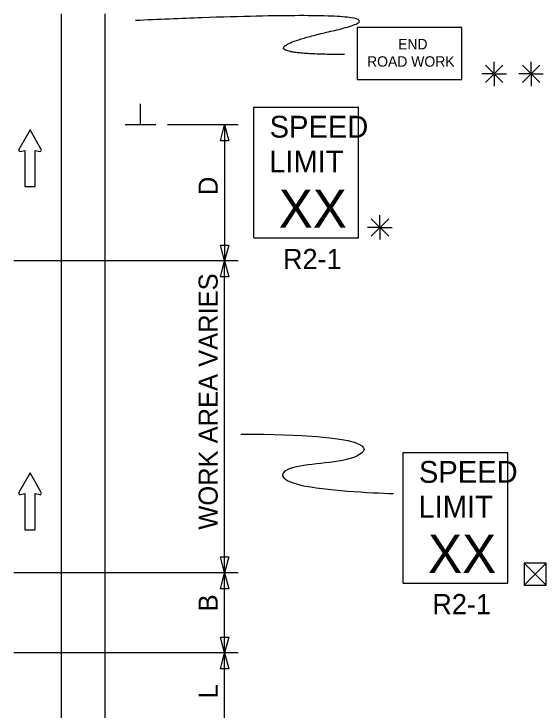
# Model space of a CAD drawing. Extents: x 16364 to 18480, y 5564 to 6927.
# Drawn here: x 16936.6 to 17132, y 6671 to 6926.7 of the extents above; entities that cross this region are included whole.
import ezdxf

# ---------------------------------------------------------------- set-up
doc = ezdxf.new("R2010")
doc.units = 0
for name, color, linetype in [('MT_SCRATCH_LEVEL_E', 7, 'Continuous'), ('PAVT_EDGE_EX', 7, 'Continuous'), ('TRAFFIC_SIGNS_PR', 7, 'Continuous'), ('TYPICAL_TEXT_DIMEN_PR', 7, 'Continuous')]:
    doc.layers.add(name, color=color, linetype=linetype)

msp = doc.modelspace()

# ---------------------------------------------------------------- linework, layer by layer
at = {"layer": 'MT_SCRATCH_LEVEL_E'}
for p, q in [((16942.49, 6884.13), (16938.38, 6876.89)), ((16946.64, 6876.89), (16942.49, 6884.13)), ((16938.86, 6876.2), (16940.64, 6876.52)), ((16940.64, 6876.52), (16940.64, 6863.26)), ((16944.38, 6863.26), (16944.38, 6876.52)), ((16944.38, 6876.52), (16946.16, 6876.2)), ((16940.64, 6863.26), (16944.38, 6863.26)), ((16942.49, 6758.11), (16938.38, 6750.87)), ((16946.64, 6750.87), (16942.49, 6758.11)), ((16938.86, 6750.18), (16940.64, 6750.5)), ((16940.64, 6750.5), (16940.64, 6737.24)), ((16944.38, 6737.24), (16944.38, 6750.5)), ((16944.38, 6750.5), (16946.16, 6750.18)), ((16940.64, 6737.24), (16944.38, 6737.24))]:
    msp.add_line(p, q, dxfattribs=at)
for centre, start, end in [((16938.79, 6876.66), 150.4248, 279.9638), ((16946.23, 6876.66), 260.0362, 29.7731), ((16938.79, 6750.64), 150.4248, 279.9638), ((16946.23, 6750.64), 260.0362, 29.7731)]:
    msp.add_arc(centre, 0.463, start, end, dxfattribs=at)
at = {"layer": 'PAVT_EDGE_EX'}
for p, q in [((16953.97, 6926.69), (16953.97, 5953.59)), ((16969.97, 6926.69), (16969.97, 5953.59))]:
    msp.add_line(p, q, dxfattribs=at)
at = {"layer": 'TRAFFIC_SIGNS_PR'}
for p, q in [((17024.72, 6892.4), (17063.12, 6892.4)), ((17024.72, 6844.4), (17024.72, 6892.4)), ((17063.12, 6844.4), (17063.12, 6892.4)), ((17024.72, 6844.4), (17063.12, 6844.4)), ((17079.58, 6765.64), (17117.98, 6765.64)), ((17079.58, 6717.64), (17079.58, 6765.64)), ((17117.98, 6717.64), (17117.98, 6765.64)), ((17079.58, 6717.64), (17117.98, 6717.64))]:
    msp.add_line(p, q, dxfattribs=at)
msp.add_lwpolyline([(17062.69, 6902.56), (17101.09, 6902.56), (17101.09, 6921.76), (17062.69, 6921.76)], close=True, dxfattribs=at)
msp.add_open_spline([(17057.97, 6911.79), (17015.46, 6911.79), (17091.98, 6929.21), (16981.19, 6924.27)], degree=2, dxfattribs=at)
at = {"layer": 'TYPICAL_TEXT_DIMEN_PR'}
for p, q in [((17113.02, 6904.69), (17113.02, 6909.14)), ((17126.53, 6904.69), (17126.53, 6909.14)), ((17116.21, 6907.88), (17109.83, 6901.5)), ((17109.84, 6907.88), (17116.21, 6901.5)), ((17123.34, 6907.88), (17129.72, 6901.5)), ((17129.72, 6907.88), (17123.34, 6901.5)), ((17113.02, 6904.69), (17108.49, 6904.69)), ((17113.02, 6904.69), (17116.21, 6904.69)), ((17113.02, 6904.69), (17117.5, 6904.69)), ((17113.02, 6904.69), (17113.02, 6900.19)), ((17126.53, 6904.69), (17122, 6904.69)), ((17126.53, 6904.69), (17129.72, 6904.69)), ((17126.53, 6904.69), (17131.01, 6904.69)), ((17126.53, 6904.69), (17126.53, 6900.19)), ((16983.09, 6885.95), (16983.09, 6893.73)), ((16988.72, 6885.95), (16977.47, 6885.95)), ((17018.97, 6885.95), (16992.97, 6885.95)), ((17012.4, 6880.08), (17013.97, 6885.95)), ((17013.97, 6885.95), (17013.97, 6835.95)), ((17013.97, 6885.95), (17015.54, 6880.08)), ((17013.97, 6880.08), (17012.4, 6880.08)), ((17015.54, 6880.08), (17013.97, 6880.08)), ((17071.04, 6848.31), (17071.04, 6852.76)), ((17074.23, 6851.49), (17067.85, 6845.12)), ((17067.86, 6851.49), (17074.23, 6845.12)), ((17071.04, 6848.31), (17066.51, 6848.31)), ((17071.04, 6848.31), (17074.23, 6848.31)), ((17071.04, 6848.31), (17075.52, 6848.31)), ((17071.04, 6848.31), (17071.04, 6843.81)), ((17013.97, 6835.95), (17012.4, 6841.81)), ((17012.4, 6841.81), (17013.97, 6841.81)), ((17013.97, 6841.81), (17015.54, 6841.81)), ((17015.54, 6841.81), (17013.97, 6835.95)), ((17018.97, 6835.95), (16936.57, 6835.95)), ((17012.4, 6830.08), (17013.97, 6835.95)), ((17013.97, 6721.41), (17013.97, 6835.95)), ((17013.97, 6835.95), (17015.54, 6830.08)), ((17013.97, 6830.08), (17012.4, 6830.08)), ((17015.54, 6830.08), (17013.97, 6830.08)), ((17013.97, 6721.41), (17012.4, 6727.27)), ((17012.4, 6727.27), (17013.97, 6727.27)), ((17013.97, 6727.27), (17015.54, 6727.27)), ((17015.54, 6727.27), (17013.97, 6721.41)), ((17124.05, 6724.91), (17132.05, 6716.91)), ((17124.05, 6716.91), (17132.05, 6724.91)), ((17018.97, 6721.41), (16936.57, 6721.41)), ((17012.4, 6715.55), (17013.97, 6721.41)), ((17013.97, 6691.98), (17013.97, 6721.41)), ((17013.97, 6721.41), (17015.54, 6715.55)), ((17013.97, 6715.55), (17012.4, 6715.55)), ((17015.54, 6715.55), (17013.97, 6715.55)), ((17013.97, 6691.98), (17012.4, 6697.84)), ((17012.4, 6697.84), (17013.97, 6697.84)), ((17013.97, 6697.84), (17015.54, 6697.84)), ((17015.54, 6697.84), (17013.97, 6691.98)), ((17018.97, 6691.98), (16936.57, 6691.98)), ((17012.4, 6686.12), (17013.97, 6691.98)), ((17013.97, 6661.42), (17013.97, 6691.98)), ((17013.97, 6691.98), (17015.54, 6686.12)), ((17013.97, 6686.12), (17012.4, 6686.12)), ((17015.54, 6686.12), (17013.97, 6686.12))]:
    msp.add_line(p, q, dxfattribs=at)
msp.add_lwpolyline([(17124.05, 6724.91), (17124.05, 6716.91), (17132.05, 6716.91), (17132.05, 6724.91)], close=True, dxfattribs=at)
msp.add_open_spline([(17019.91, 6772.38), (17068.38, 6772.38), (17068.38, 6761.62), (17033.46, 6761.62), (17033.46, 6752.57), (17067.67, 6750.81), (17075.96, 6750.52)], degree=3, dxfattribs=at)

# ---------------------------------------------------------------- texts
at = {"layer": 'TRAFFIC_SIGNS_PR'}
for s, height, p in [('END', 3.831, (17077.69, 6913.69)), ('ROAD WORK', 3.831, (17066.29, 6907.31)), ('SPEED', 8, (17030.49, 6881.27)), ('LIMIT', 8, (17030.33, 6868.47)), ('XX', 14.031, (17033.84, 6848.16)), ('R2-1', 7.44, (17035.4, 6832.96)), ('SPEED', 8, (17085.34, 6754.5)), ('LIMIT', 8, (17085.18, 6741.7)), ('XX', 14.031, (17088.69, 6721.4)), ('R2-1', 7.44, (17090.25, 6706.2))]:
    msp.add_text(s, height=height, dxfattribs=at).set_placement(p)
at = {"layer": 'TYPICAL_TEXT_DIMEN_PR'}
for s, p in [('D', (17011.41, 6860.17)), ('WORK AREA VARIES', (17011.41, 6737.26)), ('B', (17011.41, 6707.25)), ('L', (17011.41, 6675.28))]:
    msp.add_text(s, height=7, rotation=90, dxfattribs=at).set_placement(p)

doc.saveas('drawing.dxf')
